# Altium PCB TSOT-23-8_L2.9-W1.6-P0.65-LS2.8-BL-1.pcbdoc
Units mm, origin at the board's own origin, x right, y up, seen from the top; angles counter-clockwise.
Board outline 15.77 x 16.32 mm, 2 copper layers (Top Layer, Bottom Layer), stack 0 mm thick; 1 components, 0 nets, 8 pads, 0 vias.
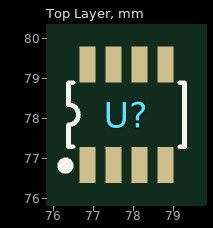
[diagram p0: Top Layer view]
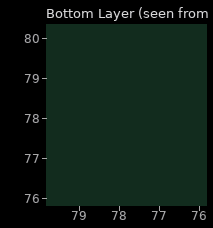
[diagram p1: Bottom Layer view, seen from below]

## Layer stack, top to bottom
Top Layer: signal copper (thickness not stored)
Bottom Layer: signal copper (thickness not stored)

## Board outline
85.624,69.85 69.85,69.85 69.85,86.165 85.624,86.165

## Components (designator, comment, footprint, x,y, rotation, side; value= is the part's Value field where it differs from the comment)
U? "" TSOT-23-8_L2.9-W1.6-P0.65-LS2.8-BL-1 77.824,78.105 r0 top

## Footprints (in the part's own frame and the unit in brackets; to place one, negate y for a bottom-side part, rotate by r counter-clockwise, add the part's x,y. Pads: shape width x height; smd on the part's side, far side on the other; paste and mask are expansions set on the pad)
TSOT-23-8_L2.9-W1.6-P0.65-LS2.8-BL-1 [mm]
  rect 0.4x0.9 smd: 1(-0.975,-1.26) 2(-0.325,-1.26) 3(0.325,-1.26) 4(0.975,-1.26) 5(0.975,1.26) 6(0.325,1.26) 7(-0.325,1.26) 8(-0.975,1.26)
  silkscreen extent -1.62,-1.37 1.45,0.8

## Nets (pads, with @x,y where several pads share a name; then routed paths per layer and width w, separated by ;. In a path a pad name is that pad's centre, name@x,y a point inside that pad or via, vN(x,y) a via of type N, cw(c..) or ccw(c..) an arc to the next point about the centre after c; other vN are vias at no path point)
pads on no net: U?.1 U?.2 U?.3 U?.4 U?.5 U?.6 U?.7 U?.8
